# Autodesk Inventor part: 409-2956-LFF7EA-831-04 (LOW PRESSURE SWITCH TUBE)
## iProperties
Created: 2011-01
Part Number: 409-2956-LFF7EA-831-04 (LOW PRESSURE SWITCH TUBE)
Material: 3/8" OD TUBE - SS
Document SubType Name: Modeling
Designer: S. Boerckel
Engineer: Steve Boerckel
Mass: 199.016 g
Surface Area: 326.016 cm^2
Volume: 24.784 cm^3
Density: 8.03 g/cm^3
Author: S. Boerckel
Revision Number: 0
LGTH: 25.472 in
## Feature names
1. Sweep1
